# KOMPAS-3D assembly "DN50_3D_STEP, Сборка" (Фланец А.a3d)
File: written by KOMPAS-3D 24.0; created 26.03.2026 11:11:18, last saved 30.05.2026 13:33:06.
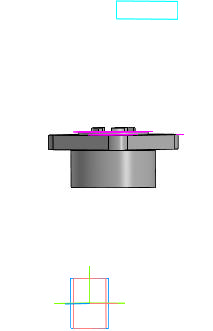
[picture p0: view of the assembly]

Document properties: Автор: R2D2; Полное имя файла: E:\Работа\Зайцев\GVWR2121M-2W-F-ОСТ Задвижка клиновая 30с964нж DN.ru Ду50-300 Ру25\исходные материалы\DN80\Фланец А.a3d

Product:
- Body: Тело 2  | qty 1
    Масса: 2.709631
- Part/product: DN50_3D_STEP  | designation Сборка
    Масса: 2.725126

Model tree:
1. Перпендикулярная плоскость:2
     Координата Z = -90
2. Операция без истории:2
3. Эскиз:1  (with: Грань.Операция без истории:2, Ребро.Операция без истории:2)
4. Элемент выдавливания:1  (with: Грань.Операция без истории:2)
     Расстояние 2 = 14.5
5. Массив по концентрической сетке:1  (with: Элемент выдавливания:1, Грань.Операция без истории:2)  (4 pattern instances)
     Шаг 2 = 360
6. Скругление:1
     Радиус = 13.5
7. Эскиз:2  (with: Грань.Операция без истории:2, Ребро.Операция без истории:2)
8. Элемент выдавливания:2
     Расстояние 2 = 20
9. Эскиз:3  (with: Грань.Операция без истории:2, Ребро.Операция без истории:2)
10. Элемент выдавливания:3  (with: Грань.Операция без истории:2)
     Расстояние 2 = 3
11. Эскиз:4  (with: Грань.Операция без истории:2, Ребро.Операция без истории:2)
12. Элемент выдавливания:4
     Расстояние 1 = 3
13. Эскиз:5  (with: Грань.Операция без истории:2, Ребро.Операция без истории:2)
14. Элемент выдавливания:5
     Расстояние 1 = 1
